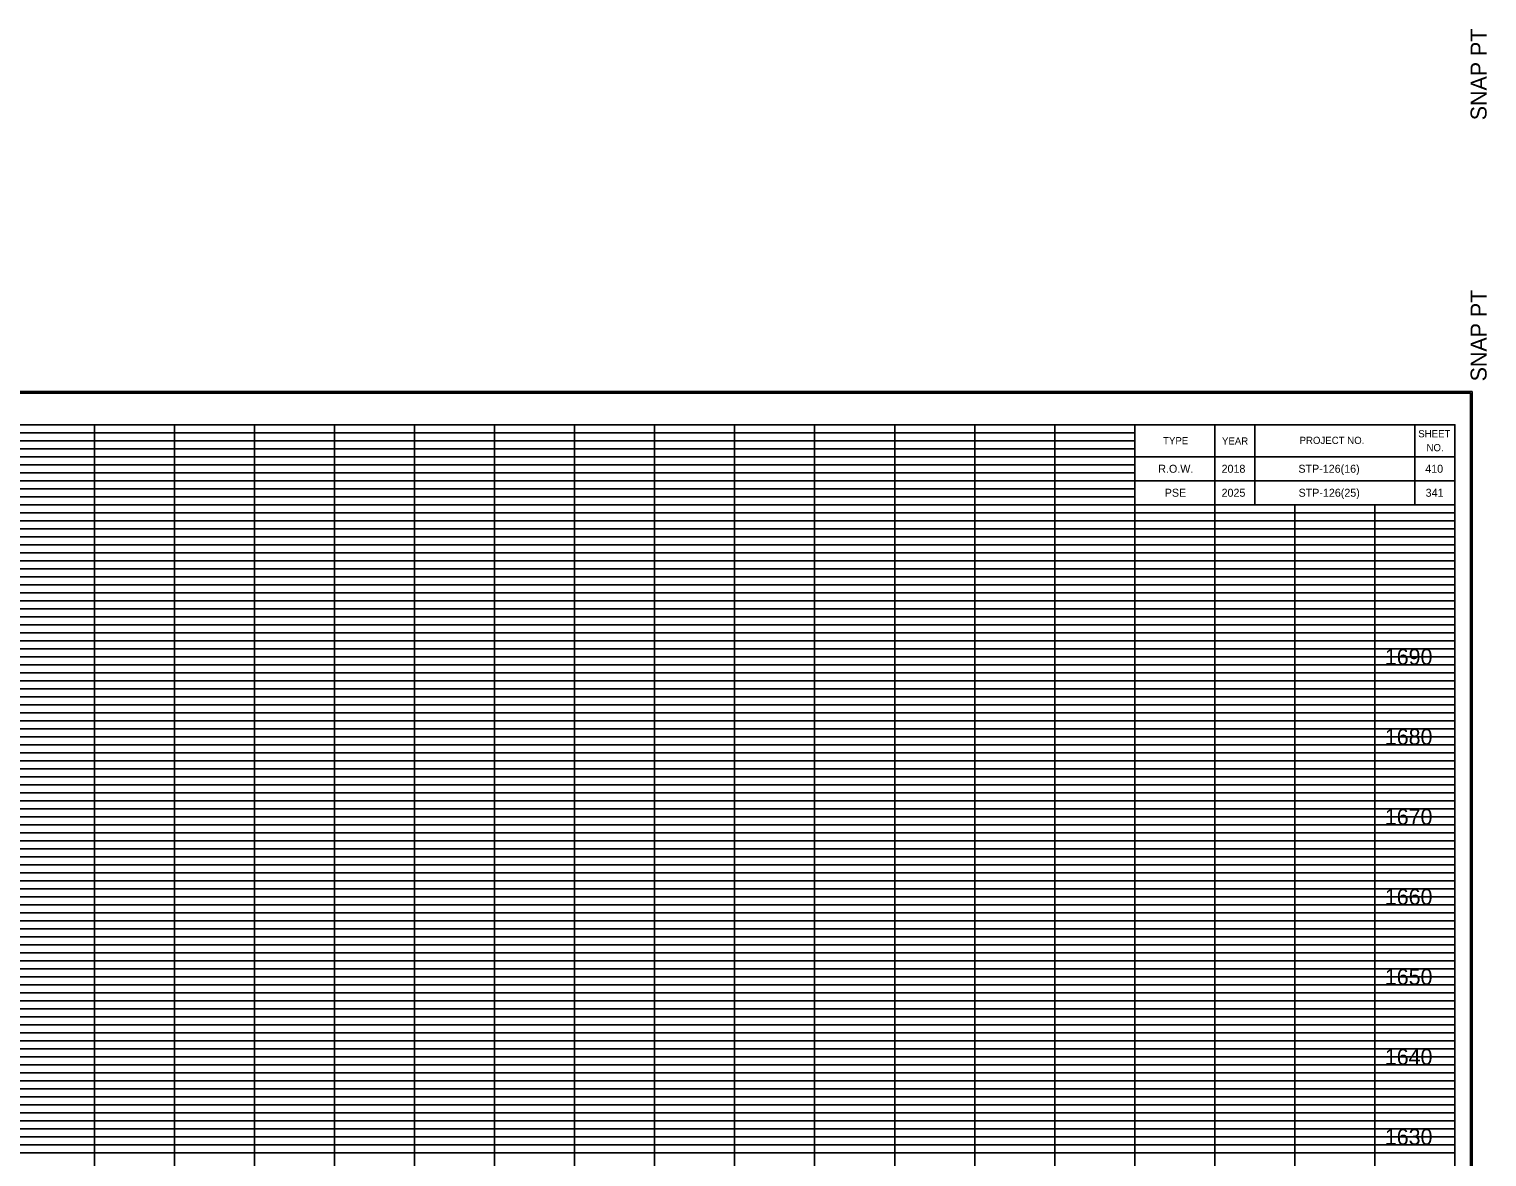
# Model space of a CAD drawing. Extents: x 980 to 1324, y 978 to 1767.
# Drawn here: x 1141.8 to 1324, y 1118.5 to 1259.4 of the extents above; entities that cross this region are included whole.
import ezdxf

# ---------------------------------------------------------------- set-up
doc = ezdxf.new("R2010")
doc.units = 0
for name, color, linetype in [('DESIGN - SCRATCH - User 1', 7, 'Continuous'), ('DESIGN - SHEET - Corner Text', 7, 'Continuous'), ('DESIGN - SHEET - Light Grid', 7, 'Continuous'), ('DESIGN - SHEET - Linework', 7, 'Continuous'), ('DESIGN - SHEET - Plot Shape', 7, 'Continuous'), ('DESIGN - TYPICAL - Finished Grade and Subgrade', 7, 'Continuous')]:
    doc.layers.add(name, color=color, linetype=linetype)

# ---------------------------------------------------------------- blocks, each defined once
blk = doc.blocks.new('XSTSHT')
at = {"layer": 'DESIGN - SCRATCH - User 1'}
for p, q in [((28.5, 20.45), (28.5, 20.45)), ((29.24, 20.45), (29.24, 20.45)), ((30.49, 20.45), (30.49, 20.45)), ((31.74, 20.45), (31.74, 20.45)), ((28.5, 20.15), (28.5, 20.15)), ((29.24, 20.15), (29.24, 20.15)), ((30.49, 20.15), (30.49, 20.15)), ((31.74, 20.15), (31.74, 20.15))]:
    blk.add_line(p, q, dxfattribs=at)
at = {"layer": 'DESIGN - SHEET - Light Grid'}
for p, q in [((8, 20.9), (16, 20.9)), ((8, 20.8), (16, 20.8)), ((16, 20.9), (24, 20.9)), ((16, 20.8), (24, 20.8)), ((24, 20.9), (28, 20.9)), ((24, 20.8), (28, 20.8)), ((8, 20.7), (16, 20.7)), ((8, 20.6), (16, 20.6)), ((16, 20.7), (24, 20.7)), ((16, 20.6), (24, 20.6)), ((24, 20.7), (28, 20.7)), ((24, 20.6), (28, 20.6)), ((8, 20.5), (16, 20.5)), ((16, 20.5), (24, 20.5)), ((24, 20.5), (28, 20.5)), ((8, 20.4), (16, 20.4)), ((8, 20.3), (16, 20.3)), ((16, 20.4), (24, 20.4)), ((16, 20.3), (24, 20.3)), ((24, 20.4), (28, 20.4)), ((24, 20.3), (28, 20.3)), ((8, 20.2), (16, 20.2)), ((8, 20.1), (16, 20.1)), ((16, 20.2), (24, 20.2)), ((16, 20.1), (24, 20.1)), ((24, 20.2), (28, 20.2)), ((24, 20.1), (28, 20.1)), ((8, 19.9), (16, 19.9)), ((16, 19.9), (24, 19.9)), ((24, 19.9), (32, 19.9)), ((8, 19.8), (16, 19.8)), ((8, 19.7), (16, 19.7)), ((16, 19.8), (24, 19.8)), ((16, 19.7), (24, 19.7)), ((24, 19.8), (32, 19.8)), ((24, 19.7), (32, 19.7)), ((8, 19.6), (16, 19.6)), ((8, 19.5), (16, 19.5)), ((16, 19.6), (24, 19.6)), ((16, 19.5), (24, 19.5)), ((24, 19.6), (32, 19.6)), ((24, 19.5), (32, 19.5)), ((8, 19.4), (16, 19.4)), ((16, 19.4), (24, 19.4)), ((24, 19.4), (32, 19.4)), ((8, 19.3), (16, 19.3)), ((8, 19.2), (16, 19.2)), ((16, 19.3), (24, 19.3)), ((16, 19.2), (24, 19.2)), ((24, 19.3), (32, 19.3)), ((24, 19.2), (32, 19.2)), ((8, 19.1), (16, 19.1)), ((16, 19.1), (24, 19.1)), ((24, 19.1), (32, 19.1)), ((8, 18.9), (16, 18.9)), ((8, 18.8), (16, 18.8)), ((16, 18.9), (24, 18.9)), ((16, 18.8), (24, 18.8)), ((24, 18.9), (32, 18.9)), ((24, 18.8), (32, 18.8)), ((8, 18.7), (16, 18.7)), ((8, 18.6), (16, 18.6)), ((16, 18.7), (24, 18.7)), ((16, 18.6), (24, 18.6)), ((24, 18.7), (32, 18.7)), ((24, 18.6), (32, 18.6)), ((8, 18.5), (16, 18.5)), ((8, 18.4), (16, 18.4)), ((16, 18.5), (24, 18.5)), ((16, 18.4), (24, 18.4)), ((24, 18.5), (32, 18.5)), ((24, 18.4), (32, 18.4)), ((8, 18.3), (16, 18.3)), ((16, 18.3), (24, 18.3)), ((24, 18.3), (32, 18.3)), ((8, 18.2), (16, 18.2)), ((8, 18.1), (16, 18.1)), ((16, 18.2), (24, 18.2)), ((16, 18.1), (24, 18.1)), ((24, 18.2), (32, 18.2)), ((24, 18.1), (32, 18.1)), ((8, 17.9), (16, 17.9)), ((16, 17.9), (24, 17.9)), ((24, 17.9), (32, 17.9)), ((8, 17.8), (16, 17.8)), ((8, 17.7), (16, 17.7)), ((16, 17.8), (24, 17.8)), ((16, 17.7), (24, 17.7)), ((24, 17.8), (32, 17.8)), ((24, 17.7), (32, 17.7)), ((8, 17.6), (16, 17.6)), ((8, 17.5), (16, 17.5)), ((16, 17.6), (24, 17.6)), ((16, 17.5), (24, 17.5)), ((24, 17.6), (32, 17.6)), ((24, 17.5), (32, 17.5)), ((8, 17.4), (16, 17.4)), ((16, 17.4), (24, 17.4)), ((24, 17.4), (32, 17.4)), ((8, 17.3), (16, 17.3)), ((8, 17.2), (16, 17.2)), ((16, 17.3), (24, 17.3)), ((16, 17.2), (24, 17.2)), ((24, 17.3), (32, 17.3)), ((24, 17.2), (32, 17.2)), ((8, 17.1), (16, 17.1)), ((16, 17.1), (24, 17.1)), ((24, 17.1), (32, 17.1)), ((8, 16.9), (16, 16.9)), ((8, 16.8), (16, 16.8)), ((16, 16.9), (24, 16.9)), ((16, 16.8), (24, 16.8)), ((24, 16.9), (32, 16.9)), ((24, 16.8), (32, 16.8)), ((8, 16.7), (16, 16.7)), ((8, 16.6), (16, 16.6)), ((16, 16.7), (24, 16.7)), ((16, 16.6), (24, 16.6)), ((24, 16.7), (32, 16.7)), ((24, 16.6), (32, 16.6)), ((8, 16.5), (16, 16.5)), ((8, 16.4), (16, 16.4)), ((16, 16.5), (24, 16.5)), ((16, 16.4), (24, 16.4)), ((24, 16.5), (32, 16.5)), ((24, 16.4), (32, 16.4)), ((8, 16.3), (16, 16.3)), ((16, 16.3), (24, 16.3)), ((24, 16.3), (32, 16.3)), ((8, 16.2), (16, 16.2)), ((8, 16.1), (16, 16.1)), ((16, 16.2), (24, 16.2)), ((16, 16.1), (24, 16.1)), ((24, 16.2), (32, 16.2)), ((24, 16.1), (32, 16.1)), ((8, 15.9), (16, 15.9)), ((16, 15.9), (24, 15.9)), ((24, 15.9), (32, 15.9)), ((8, 15.8), (16, 15.8)), ((8, 15.7), (16, 15.7)), ((16, 15.8), (24, 15.8)), ((16, 15.7), (24, 15.7)), ((24, 15.8), (32, 15.8)), ((24, 15.7), (32, 15.7)), ((8, 15.6), (16, 15.6)), ((8, 15.5), (16, 15.5)), ((16, 15.6), (24, 15.6)), ((16, 15.5), (24, 15.5)), ((24, 15.6), (32, 15.6)), ((24, 15.5), (32, 15.5)), ((8, 15.4), (16, 15.4)), ((16, 15.4), (24, 15.4)), ((24, 15.4), (32, 15.4)), ((8, 15.3), (16, 15.3)), ((8, 15.2), (16, 15.2)), ((16, 15.3), (24, 15.3)), ((16, 15.2), (24, 15.2)), ((24, 15.3), (32, 15.3)), ((24, 15.2), (32, 15.2)), ((8, 15.1), (16, 15.1)), ((16, 15.1), (24, 15.1)), ((24, 15.1), (32, 15.1)), ((8, 14.9), (16, 14.9)), ((8, 14.8), (16, 14.8)), ((16, 14.9), (24, 14.9)), ((16, 14.8), (24, 14.8)), ((24, 14.9), (32, 14.9)), ((24, 14.8), (32, 14.8)), ((8, 14.7), (16, 14.7)), ((8, 14.6), (16, 14.6)), ((16, 14.7), (24, 14.7)), ((16, 14.6), (24, 14.6)), ((24, 14.7), (32, 14.7)), ((24, 14.6), (32, 14.6)), ((8, 14.5), (16, 14.5)), ((8, 14.4), (16, 14.4)), ((16, 14.5), (24, 14.5)), ((16, 14.4), (24, 14.4)), ((24, 14.5), (32, 14.5)), ((24, 14.4), (32, 14.4)), ((8, 14.3), (16, 14.3)), ((16, 14.3), (24, 14.3)), ((24, 14.3), (32, 14.3)), ((8, 14.2), (16, 14.2)), ((8, 14.1), (16, 14.1)), ((16, 14.2), (24, 14.2)), ((16, 14.1), (24, 14.1)), ((24, 14.2), (32, 14.2)), ((24, 14.1), (32, 14.1)), ((8, 13.9), (16, 13.9)), ((16, 13.9), (24, 13.9)), ((24, 13.9), (32, 13.9)), ((8, 13.8), (16, 13.8)), ((8, 13.7), (16, 13.7)), ((16, 13.8), (24, 13.8)), ((16, 13.7), (24, 13.7)), ((24, 13.8), (32, 13.8)), ((24, 13.7), (32, 13.7)), ((8, 13.6), (16, 13.6)), ((8, 13.5), (16, 13.5)), ((16, 13.6), (24, 13.6)), ((16, 13.5), (24, 13.5)), ((24, 13.6), (32, 13.6)), ((24, 13.5), (32, 13.5)), ((8, 13.4), (16, 13.4)), ((8, 13.3), (16, 13.3)), ((16, 13.4), (24, 13.4)), ((16, 13.3), (24, 13.3)), ((24, 13.4), (32, 13.4)), ((24, 13.3), (32, 13.3)), ((8, 13.2), (16, 13.2)), ((16, 13.2), (24, 13.2)), ((24, 13.2), (32, 13.2)), ((8, 13.1), (16, 13.1)), ((16, 13.1), (24, 13.1)), ((24, 13.1), (32, 13.1)), ((8, 12.9), (16, 12.9)), ((8, 12.8), (16, 12.8)), ((16, 12.9), (24, 12.9)), ((16, 12.8), (24, 12.8)), ((24, 12.9), (32, 12.9)), ((24, 12.8), (32, 12.8)), ((8, 12.7), (16, 12.7)), ((8, 12.6), (16, 12.6)), ((16, 12.7), (24, 12.7)), ((16, 12.6), (24, 12.6)), ((24, 12.7), (32, 12.7)), ((24, 12.6), (32, 12.6)), ((8, 12.5), (16, 12.5)), ((8, 12.4), (16, 12.4)), ((16, 12.5), (24, 12.5)), ((16, 12.4), (24, 12.4)), ((24, 12.5), (32, 12.5)), ((24, 12.4), (32, 12.4)), ((8, 12.3), (16, 12.3)), ((16, 12.3), (24, 12.3)), ((24, 12.3), (32, 12.3)), ((8, 12.2), (16, 12.2)), ((8, 12.1), (16, 12.1)), ((16, 12.2), (24, 12.2)), ((16, 12.1), (24, 12.1)), ((24, 12.2), (32, 12.2)), ((24, 12.1), (32, 12.1)), ((8, 11.9), (16, 11.9)), ((16, 11.9), (24, 11.9)), ((24, 11.9), (32, 11.9))]:
    blk.add_line(p, q, dxfattribs=at)
at = {"layer": 'DESIGN - SHEET - Linework'}
for p, q in [((-1.823, 21.414), (32.217, 21.414)), ((32.217, 21.414), (32.217, -0.414)), ((15, 0), (15, 21)), ((16, 0), (16, 21)), ((17, 0), (17, 21)), ((18, 0), (18, 21)), ((19, 0), (19, 21)), ((20, 0), (20, 21)), ((21, 0), (21, 21)), ((22, 0), (22, 21)), ((23, 0), (23, 21)), ((24, 0), (24, 21)), ((25, 0), (25, 21)), ((26, 0), (26, 21)), ((27, 0), (27, 21)), ((0, 20), (28, 20)), ((28, 0), (28, 20)), ((29, 0), (29, 20)), ((30, 0), (30, 20)), ((31, 0), (31, 20)), ((0, 19), (32, 19)), ((0, 18), (32, 18)), ((0, 17), (32, 17)), ((0, 16), (32, 16)), ((0, 15), (32, 15)), ((0, 14), (32, 14)), ((0, 13), (32, 13)), ((0, 12), (32, 12))]:
    blk.add_line(p, q, dxfattribs=at)
for points in [[(0, 21), (0, 0), (32, 0), (32, 21), (0, 21)], [(28, 21), (28, 20), (32, 20), (32, 21), (31.5, 21), (31.5, 20), (29.5, 20), (29.5, 21), (29, 21), (29, 20), (32, 20), (28, 20), (28, 20.3), (32, 20.3), (32, 20.6), (28, 20.6)]]:
    blk.add_lwpolyline(points, dxfattribs=at)
at = {"layer": 'DESIGN - SHEET - Plot Shape'}
for points in [[(-1.803, 21.394), (32.197, 21.394), (32.197, -0.394), (-1.803, -0.394)], [(-0.85, 21), (32, 21), (32, -0.25), (-0.85, -0.25)]]:
    blk.add_lwpolyline(points, close=True, dxfattribs=at)
at = {"layer": 'DESIGN - SHEET - Corner Text'}
for s, p in [('  SNAP PT', (32.397, 21.394)), ('SNAP PT  ', (32.397, -2.194))]:
    blk.add_text(s, height=0.2, rotation=90, dxfattribs=at).set_placement(p)
for s, p in [('TYPE', (28.354, 20.756)), ('YEAR', (29.09, 20.752)), ('PROJECT NO.', (30.06, 20.76)), ('SHEET', (31.543, 20.843)), ('NO.', (31.646, 20.669))]:
    blk.add_text(s, height=0.09, dxfattribs=at).set_placement(p)

msp = doc.modelspace()

# ---------------------------------------------------------------- linework, layer by layer
at = {"layer": 'DESIGN - SHEET - Plot Shape'}
msp.add_lwpolyline([(991.5, 1210), (1320, 1210), (1320, 997.5), (991.5, 997.5)], close=True, dxfattribs=at)

# ---------------------------------------------------------------- block references
at = {"layer": 'DESIGN - TYPICAL - Finished Grade and Subgrade', "xscale": 10, "yscale": 10}
for p in [(1000, 1270), (1000, 1000)]:
    msp.add_blockref('XSTSHT', p, dxfattribs=at)

# ---------------------------------------------------------------- texts
at = {"layer": 'DESIGN - SHEET - Corner Text'}
for s, height, p in [('R.O.W.', 1, (1282.94, 1204)), ('2018', 1, (1290.85, 1204)), ('STP-126(16)', 1, (1300.45, 1204)), ('410', 1, (1316.3, 1204)), ('PSE', 1, (1283.75, 1201)), ('2025', 1, (1290.85, 1201)), ('STP-126(25)', 1, (1300.47, 1201)), ('341', 1, (1316.35, 1201)), ('1690', 2, (1311.25, 1180)), ('1680', 2, (1311.25, 1170)), ('1670', 2, (1311.25, 1160)), ('1660', 2, (1311.25, 1150)), ('1650', 2, (1311.25, 1140)), ('1640', 2, (1311.25, 1130)), ('1630', 2, (1311.25, 1120))]:
    msp.add_text(s, height=height, dxfattribs=at).set_placement(p)

doc.saveas('drawing.dxf')
